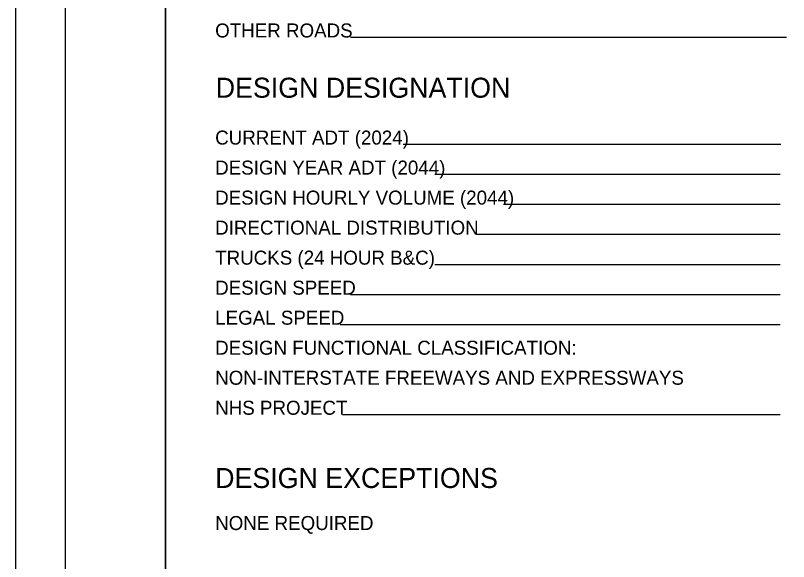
# Model space of a CAD drawing. Extents: x 39.8 to 73.8, y 13 to 35.
# Drawn here: x 39.76 to 47.48, y 18.6 to 24.06 of the extents above; entities that cross this region are included whole.
import ezdxf

# ---------------------------------------------------------------- set-up
doc = ezdxf.new("R2010")
doc.units = 0
for name, color, linetype in [('SH_Border', 7, 'Continuous'), ('SH_Cut_Line', 7, 'Continuous'), ('SH_Data', 7, 'Continuous'), ('SH_Text', 7, 'Continuous')]:
    doc.layers.add(name, color=color, linetype=linetype)

msp = doc.modelspace()

# ---------------------------------------------------------------- linework, layer by layer
at = {"layer": 'SH_Border'}
for points in [[(40.263, 34.465), (41.263, 34.465), (41.263, 13.465), (40.263, 13.465)], [(41.263, 34.465), (73.263, 34.465), (73.263, 13.465), (41.263, 13.465)]]:
    msp.add_lwpolyline(points, close=True, dxfattribs=at)
at = {"layer": 'SH_Cut_Line'}
msp.add_lwpolyline([(39.763, 12.965), (73.763, 12.965), (73.763, 34.965), (39.763, 34.965)], close=True, dxfattribs=at)
at = {"layer": 'SH_Data'}
for p, q in [((47.463, 23.8416), (43.1101, 23.8416)), ((47.4054, 22.7712), (43.634, 22.7712)), ((47.3998, 22.4712), (43.9515, 22.4712)), ((47.3998, 22.1712), (44.6353, 22.1712)), ((47.3998, 21.8712), (44.3667, 21.8712)), ((47.3998, 21.5712), (43.9515, 21.5712)), ((47.3998, 21.2712), (43.1089, 21.2712)), ((47.3998, 20.9712), (43.0051, 20.9712)), ((47.3998, 20.0712), (43.0299, 20.0712))]:
    msp.add_line(p, q, dxfattribs=at)

# ---------------------------------------------------------------- texts
msp.add_text('DESIGN DESIGNATION', height=0.2, dxfattribs=at).set_placement((41.763, 23.2396))
at = {"layer": 'SH_Text'}
for s, height, p in [('OTHER ROADS', 0.14, (41.7574, 23.8416)), ('CURRENT ADT (2024)', 0.14, (41.7574, 22.7712)), ('DESIGN YEAR ADT (2044)', 0.14, (41.7574, 22.4712)), ('DESIGN HOURLY VOLUME (2044)', 0.14, (41.7574, 22.1712)), ('DIRECTIONAL DISTRIBUTION', 0.14, (41.7574, 21.8712)), ('TRUCKS (24 HOUR B&C)', 0.14, (41.7574, 21.5712)), ('DESIGN SPEED', 0.14, (41.7574, 21.2712)), ('LEGAL SPEED', 0.14, (41.7574, 20.9712)), ('DESIGN FUNCTIONAL CLASSIFICATION:', 0.14, (41.7574, 20.6712)), ('NON-INTERSTATE FREEWAYS AND EXPRESSWAYS', 0.14, (41.7574, 20.3712)), ('NHS PROJECT', 0.14, (41.7574, 20.0712)), ('DESIGN EXCEPTIONS', 0.2, (41.7574, 19.3394)), ('NONE REQUIRED', 0.14, (41.7574, 18.9194))]:
    msp.add_text(s, height=height, dxfattribs=at).set_placement(p)

doc.saveas('drawing.dxf')
